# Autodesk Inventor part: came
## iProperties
Shininess: 64.0
Length Units: 11269
Angle Units: 11279
Time Units: 11290
Mass Units: 11283
Length Display Precision: 3
Angle Display Precision: 2
Compacted: True
Part Number: came
Document SubType Name: Modeling
Created: 2003-05
Material: Delrin - Blanc
Designer: robert
Density: 1.42 g/cm^3
Density: 0.0
Volumn: 0.0
Area: 0.0
PropertySet Name: Model Information
Control State: 0
Master: False
Checked Out: False
Author: robert
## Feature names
1. Extrusion1
2. Extrusion2
3. Extrusion3
4. Extrusion4
5. Extrusion5
